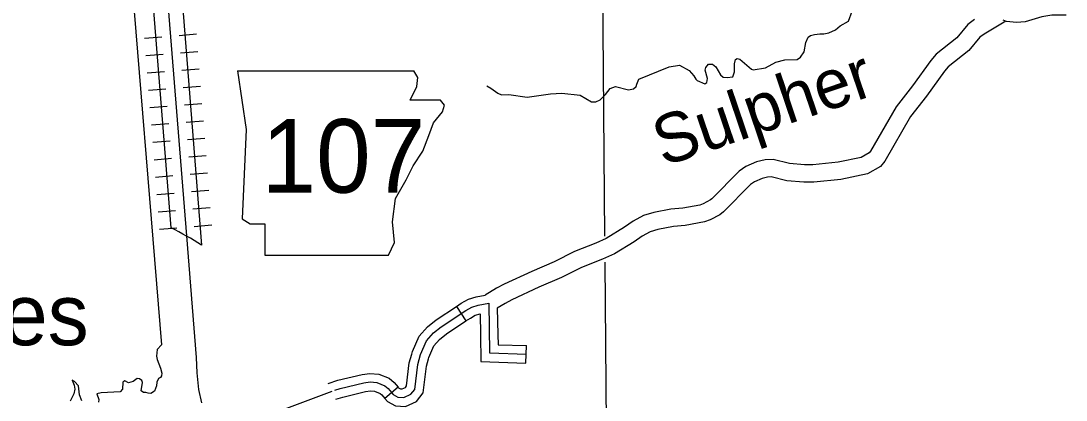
# Model space of a CAD drawing. Extents: x 1212896 to 1368412, y 378476 to 478763.
# Drawn here: x 1284025 to 1293036, y 413498 to 416764 of the extents above; entities that cross this region are included whole.
import ezdxf

# ---------------------------------------------------------------- set-up
doc = ezdxf.new("R2010")
doc.units = 0
for name, color, linetype in [('Level 10', 7, 'Continuous'), ('Level 21', 7, 'Continuous'), ('Level 24', 7, 'Continuous'), ('Level 29', 7, 'Continuous'), ('Level 32', 7, 'Continuous'), ('Level 35', 7, 'Continuous'), ('Level 45', 7, 'Continuous'), ('Level 46', 7, 'Continuous'), ('Level 5', 7, 'Continuous'), ('Level 9', 7, 'Continuous')]:
    doc.layers.add(name, color=color, linetype=linetype)

msp = doc.modelspace()

# ---------------------------------------------------------------- linework, layer by layer
at = {"layer": 'Level 10'}
for points in [[(1285320.6, 414981), (1285071.2, 418110.1), (1285025.6, 418188.5), (1284983.2, 418276), (1284957.5, 418345.8), (1284933.3, 418491.7), (1284936.7, 418595.6), (1284915.8, 421010.9)], [(1285165.8, 421016.2), (1285186.7, 418592.7), (1285184, 418508.2), (1285200.2, 418410), (1285213.5, 418374), (1285246.5, 418306), (1285313.3, 418191.1), (1285319.5, 418141.4), (1285583.2, 414833.4)], [(1285451.5, 414911.6), (1285535, 413864.7), (1285541.3, 413732.5), (1285556.8, 413589.4), (1285581.9, 413474.5)]]:
    msp.add_lwpolyline(points, dxfattribs=at)
msp.add_arc((1283958.3, 412250.8), 3051.2, 57.82224, 63.48086, dxfattribs=at)
at = {"layer": 'Level 21'}
for p, q in [((1285891.5, 416335.3), (1285967.6, 415827.7)), ((1287448, 416276), (1287412.9, 416334.5)), ((1287380.3, 416081.5), (1287439.5, 416199.9)), ((1287439.5, 416199.9), (1287448, 416276)), ((1287642.5, 416081.5), (1287380.3, 416081.5)), ((1287676.4, 416039.2), (1287642.5, 416081.5)), ((1287659.4, 415980), (1287676.4, 416039.2)), ((1287583.3, 415886.9), (1287659.4, 415980)), ((1287541, 415777), (1287583.3, 415886.9)), ((1285967.6, 415827.7), (1285933.8, 415058)), ((1287490.3, 415641.6), (1287541, 415777)), ((1287405.7, 415514.7), (1287490.3, 415641.6)), ((1287346.5, 415396.3), (1287405.7, 415514.7)), ((1287253.4, 415235.6), (1287346.5, 415396.3)), ((1287228, 415032.6), (1287253.4, 415235.6)), ((1285933.8, 415058), (1286001.5, 415015.7)), ((1287244.9, 414854.9), (1287228, 415032.6)), ((1286001.5, 415015.7), (1286128.4, 415015.7)), ((1286128.4, 415015.7), (1286128.4, 414745)), ((1287194.2, 414745), (1287244.9, 414854.9)), ((1286128.4, 414745), (1287194.2, 414745))]:
    msp.add_line(p, q, dxfattribs=at)
msp.add_lwpolyline([(1285891.5, 416335.3), (1287412.9, 416334.5)], dxfattribs=at)
at = {"layer": 'Level 29'}
for p, q in [((1285389.1, 416639.4), (1285538.6, 416651.3)), ((1285090, 416615.5), (1285239.5, 416627.4)), ((1285101.9, 416466), (1285251.5, 416477.9)), ((1285401, 416489.8), (1285550.5, 416501.8)), ((1285113.9, 416316.5), (1285263.4, 416328.4)), ((1285113.9, 416316.5), (1285263.4, 416328.4)), ((1285412.9, 416340.3), (1285562.4, 416352.2)), ((1285412.9, 416340.3), (1285562.4, 416352.2)), ((1285424.8, 416190.8), (1285574.4, 416202.7)), ((1285125.8, 416166.9), (1285275.3, 416178.9)), ((1285137.7, 416017.4), (1285287.2, 416029.3)), ((1285436.7, 416041.3), (1285586.3, 416053.2)), ((1285149.6, 415867.9), (1285299.1, 415879.8)), ((1285149.6, 415867.9), (1285299.1, 415879.8)), ((1285448.7, 415891.7), (1285598.2, 415903.6)), ((1285448.7, 415891.7), (1285598.2, 415903.6)), ((1285460.6, 415742.2), (1285610.1, 415754.1)), ((1285161.5, 415718.4), (1285311.1, 415730.3)), ((1285173.4, 415568.8), (1285323, 415580.8)), ((1285472.5, 415592.7), (1285622, 415604.6)), ((1285185.4, 415419.3), (1285334.9, 415431.2)), ((1285185.4, 415419.3), (1285334.9, 415431.2)), ((1285484.4, 415443.2), (1285633.9, 415455.1)), ((1285484.4, 415443.2), (1285633.9, 415455.1)), ((1285496.3, 415293.6), (1285645.9, 415305.5)), ((1285197.3, 415269.8), (1285346.8, 415281.7)), ((1285209.2, 415120.3), (1285358.7, 415132.2)), ((1285508.3, 415144.1), (1285657.8, 415156)), ((1285221.1, 414970.7), (1285370.6, 414982.7)), ((1285520.2, 414994.6), (1285669.7, 415006.5)), ((1285520.2, 414994.6), (1285669.7, 415006.5))]:
    msp.add_line(p, q, dxfattribs=at)
msp.add_lwpolyline([(1285195.1, 418128.7), (1285451.5, 414911.6)], dxfattribs=at)
at = {"layer": 'Level 32'}
msp.add_lwpolyline([(1293035.7, 416812.8), (1292913.5, 416814.6), (1292825.5, 416800.4), (1292683.1, 416757.3), (1292608.7, 416749.8), (1292522.5, 416760.2), (1292492, 416771.5)], dxfattribs=at)
at = {"layer": 'Level 35'}
for points in [[(1288076.7, 416184.7), (1288135.6, 416140.9), (1288168, 416128.6), (1288232.9, 416130.3), (1288388.7, 416107.9), (1288591.9, 416135.1), (1288687.7, 416140.7), (1288845.4, 416123.8), (1288944.7, 416067.8), (1288980.6, 416066.2), (1289019.3, 416085.6), (1289065.7, 416130.2), (1289106.1, 416180.8), (1289151.8, 416200.3), (1289261.8, 416169.4), (1289305.6, 416178.9), (1289330.3, 416198.2), (1289334.1, 416220.3), (1289353.6, 416263.6), (1289614.9, 416368.6), (1289702.5, 416382.6), (1289784.9, 416337), (1289825.2, 416290.4), (1289842.4, 416261.8), (1289856.5, 416250), (1289922.2, 416223.4), (1289939.4, 416232.8), (1289943.1, 416267.9), (1289925.4, 416339.9), (1289930.1, 416364), (1289953.8, 416391.3), (1289987.3, 416390.7), (1290014.8, 416368.9), (1290056.5, 416298.2), (1290078.6, 416280.4), (1290112.5, 416276.8), (1290161.4, 416283.3), (1290178.4, 416326.1), (1290177.2, 416394.7), (1290185.8, 416431.9), (1290200.6, 416441), (1290223.1, 416434.3), (1290322.3, 416347.2), (1290339.3, 416343.3), (1290444.3, 416361.2), (1290534.1, 416407.6), (1290609.7, 416428.4), (1290716.4, 416431.6), (1290745.1, 416450.9), (1290776.6, 416496.3), (1290791.7, 416576.7), (1290812.2, 416624), (1290833, 416639.2), (1290867.8, 416646.6), (1290913.6, 416653.1), (1290948.1, 416652.4), (1290990.1, 416660.1), (1291046.9, 416686.6), (1291087.5, 416721.1), (1291159.2, 416760.4), (1291190.9, 416848.5)], [(1288042.4, 416206.1), (1288076.7, 416184.7)]]:
    msp.add_lwpolyline(points, dxfattribs=at)
at = {"layer": 'Level 45'}
for p, q in [((1287779.7, 414304.8), (1287862.2, 414179.6)), ((1288379.1, 413817.1), (1288382.8, 413967.1)), ((1287276.8, 413610.5), (1287162.7, 413513.1))]:
    msp.add_line(p, q, dxfattribs=at)
for points in [[(1287779.7, 414304.8), (1287821.4, 414332.3), (1287883.1, 414367.5), (1287950.8, 414387.4), (1288026.9, 414401.9)], [(1286731.6, 413582.6), (1286778.6, 413597.6), (1286981.4, 413646.2), (1287035.7, 413654.5), (1287092.2, 413649), (1287161.3, 413621.7), (1287191.5, 413597), (1287233.8, 413547.4), (1287276, 413523.8), (1287326.9, 413520.3), (1287387, 413548.1), (1287421, 413590.5), (1287445.7, 413805.2), (1287470, 413891.1), (1287520.4, 414008.4), (1287581.6, 414076.2), (1287648.7, 414130.4), (1287859.9, 414269.5), (1287912.1, 414299.3), (1287968.1, 414315.8), (1288057.7, 414332.8), (1288066.1, 413904), (1288383.4, 413893.4)], [(1287394.5, 413894.4), (1287400.5, 413915.7), (1287457.6, 414048.6), (1287530.8, 414129.7), (1287605.1, 414189.9), (1287779.7, 414304.8)], [(1287862.2, 414179.6), (1287899.8, 414204.4), (1287942.2, 414228.5), (1287983.1, 414240.6), (1287986.7, 414060.6)], [(1288132.2, 414290.5), (1288136.6, 414063.6)], [(1287538.8, 413853.5), (1287542.2, 413865.5), (1287585.6, 413966.6), (1287634.3, 414020.6), (1287693.8, 414068.7), (1287862.2, 414179.6)], [(1287986.7, 414060.6), (1287991.2, 413830.1), (1288379.1, 413817.1)], [(1288136.6, 414063.6), (1288138.4, 413975.3), (1288382.8, 413967.1)], [(1287276.8, 413610.5), (1287281.3, 413605.2), (1287297.5, 413596.1), (1287313.2, 413595), (1287340.4, 413607.6), (1287350.3, 413620), (1287373.3, 413819.5), (1287394.5, 413894.4)], [(1287162.7, 413513.1), (1287184.6, 413487.4), (1287253.7, 413448.7), (1287341.3, 413442.8), (1287435.4, 413486.3), (1287494.3, 413559.9), (1287520.9, 413790.3), (1287538.8, 413853.5)], [(1286674.2, 413641.5), (1286758.7, 413668.5), (1286967.3, 413718.5), (1287033.6, 413728.6), (1287109.6, 413721.3), (1287199.1, 413686), (1287243.2, 413649.8), (1287276.8, 413610.5)], [(1286317.5, 413428.3), (1286707.2, 413574.9)], [(1286739.8, 413505), (1286799.1, 413524), (1286996.1, 413571.2), (1287037.8, 413577.5), (1287074.2, 413574), (1287122.2, 413555.1), (1287137.8, 413542.2), (1287162.7, 413513.1)]]:
    msp.add_lwpolyline(points, dxfattribs=at)
at = {"layer": 'Level 46'}
for points in [[(1292244.9, 416775.5), (1292189, 416734.3), (1292092.6, 416617.1), (1291914.9, 416477.2), (1291869.8, 416423.7), (1291711.6, 416205.4), (1291570.4, 416024.6), (1291348.6, 415641.6), (1291336.6, 415627.4), (1291269.8, 415588.7), (1291071.8, 415546.8), (1290851.9, 415524.7), (1290781.2, 415524.3), (1290651.9, 415535), (1290509.7, 415570.7), (1290441.8, 415568.5), (1290365.8, 415549.4), (1290274.6, 415510), (1290218.3, 415470.1), (1289982.1, 415231.2), (1289969.8, 415221.8), (1289906.2, 415188.2), (1289878.9, 415178.1), (1289731.5, 415151.7), (1289629.5, 415141.6), (1289480.8, 415113.6), (1289393.3, 415086.7), (1289302.6, 415038.7), (1289228.3, 414986.7), (1289070.9, 414889.5), (1288980.8, 414849.1), (1288796.5, 414777.4), (1288621.6, 414689.8), (1288428.9, 414607), (1288192, 414496.2), (1288125.3, 414462.4), (1288026.9, 414401.9)], [(1292515.8, 416762.7), (1292328.1, 416650.5), (1292293, 416624.6), (1292198.2, 416509.3), (1292019.7, 416368.8), (1291988, 416331.2), (1291831.4, 416115.3), (1291695, 415940.4), (1291471.8, 415555.1), (1291434.5, 415510.7), (1291324.2, 415446.9), (1291094.9, 415398.4), (1290859.9, 415374.8), (1290775.5, 415374.2), (1290627.3, 415386.5), (1290493.5, 415420.1), (1290462.7, 415419.1), (1290414.2, 415406.9), (1290348.5, 415378.5), (1290315.7, 415355.3), (1290081.3, 415118.2), (1290050.8, 415095), (1289967.6, 415050.9), (1289918.5, 415032.8), (1289752.1, 415003), (1289650.8, 414992.9), (1289516.8, 414967.8), (1289450.9, 414947.5), (1289381, 414910.5), (1289310.8, 414861.3), (1289141.2, 414756.6), (1289038.7, 414710.7), (1288857.4, 414640.2), (1288684.9, 414553.7), (1288490.3, 414470.1), (1288257.7, 414361.3), (1288198.6, 414331.4), (1288132.2, 414290.5)]]:
    msp.add_lwpolyline(points, dxfattribs=at)
at = {"layer": 'Level 5'}
for points in [[(1289040.1, 417047.1), (1289057.2, 414910.3)], [(1289059, 414686.7), (1289081.5, 411882.1)]]:
    msp.add_lwpolyline(points, dxfattribs=at)
at = {"layer": 'Level 9'}
for points in [[(1284940.9, 417583.5), (1285236.8, 413974.5)], [(1285236.8, 413974.5), (1285198.7, 413934.3), (1285193.3, 413875.1), (1285198.6, 413847.1), (1285229.3, 413772.3), (1285238.7, 413731.3), (1285236.9, 413706.2), (1285228.1, 413693.1), (1285210.2, 413682.9), (1285196.6, 413653.7), (1285194.9, 413619.6), (1285177.4, 413576.3), (1285145.7, 413554.9), (1285122.7, 413556.7), (1285101.4, 413564.1)], [(1285101.4, 413564.1), (1285082.2, 413564.3), (1285062.1, 413578.1), (1285072.4, 413649.3), (1285067.2, 413666.3), (1285048.1, 413682.2), (1285027.1, 413684.9), (1284991.5, 413658.5)], [(1284550.3, 413492.4), (1284530.9, 413543.3), (1284522.1, 413622.4), (1284486.8, 413657.1), (1284467.7, 413668.9), (1284485.1, 413628), (1284490.5, 413592), (1284480.9, 413551.8), (1284450.6, 413489.3)], [(1284991.5, 413658.5), (1284953.7, 413647.1), (1284920.6, 413663.7), (1284902.8, 413653.5), (1284900.4, 413592.4), (1284879.7, 413569.1), (1284718.2, 413559.4), (1284679.4, 413550.9), (1284696.9, 413502), (1284693.1, 413480.9)]]:
    msp.add_lwpolyline(points, dxfattribs=at)

# ---------------------------------------------------------------- texts
at = {"layer": 'Level 21'}
msp.add_text('107', height=633.6, dxfattribs=at).set_placement((1286098.5, 415284.6))
at = {"layer": 'Level 24'}
msp.add_text('Shores', height=528, dxfattribs=at).set_placement((1282372.3, 413970.6))
at = {"layer": 'Level 35'}
msp.add_text('Sulpher', height=422.4, rotation=18.7323, dxfattribs=at).set_placement((1289562, 415507.7))

doc.saveas('drawing.dxf')
